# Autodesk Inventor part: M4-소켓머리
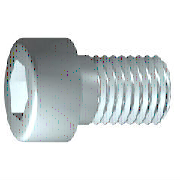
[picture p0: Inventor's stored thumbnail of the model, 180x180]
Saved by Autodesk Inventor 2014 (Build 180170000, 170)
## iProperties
IsCustomPart: 0
Created: 2009-02
Part Number: M4-소켓머리
Material: 강, 연강
Description: 6각머리 태핑 나사
Document SubType Name: Modeling
Standard: KS B 1003
Designer: 한국산업디자인학원 [http://gmhk.co.kr]
Standards Organization: KS
Language: ko-KR
Size Designation: M 4 x 12
Categories: <MemberInstance><Categories><Category DisplayName="조임쇠" InternalName="e4da775c-781d-43d5-af7c-5136215cf5a6" Mnemonic="FSTN"><Category DisplayName="볼트" InternalN
Density: 7.86 g/cm^3
Mass: 2.23465 g
Surface Area: 3.30853 cm^2
Volume: 0.284306 cm^3
Appearance: _시험-금속-강(연마)
Author: pww
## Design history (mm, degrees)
sketch "스케치1"
  geometry: L1 (-1, 0)-(12, 0); L2 (12, 0)-(12, 2); L3 (12, 2)-(1.75, 2); L4 (1.75, 2)-(1.32, 2); L5 (1.32, 2)-(0, 2); L6 (0, 2)-(0, 3.5); L7 (0, 3.5)-(-4, 3.5); L8 (-4, 3.5)-(-4, 1.732); L9 (-4, 1.732)-(-2, 1.732); L10 (-2, 1.732)-(-1, 0); L11 (-7.2, 0)-(15.2, 0) reference; L12 (0, -0.7)-(0, 4.2) reference; L13 (1.75, 2)-(0, 2)
  constraints: 22 end point, 6 parallel, 2 collinear, 2 perpendicular, 1 horizontal, 1 point on line
  dimensions: "d1" = 10.25 distance from line of L3.end L2 (= GEL); "d2" = 0.42952 distance of L4.end L3.end (computed from GAL); "d3" = 4 distance between parallel lines of L8 L6 (= KOH); "d4" = 2 distance of L8.end L9.end (= INTI); "d5" = 60 deg angle of L10 L1; "d6" = 4 diameter of L3 L1 (= GD); "d7" = 4 diameter of L5 L1 (= BDM); "d8" = 3.4641 diameter of L9 L1 (= 1.1547 x SW); "d9" = 7 diameter of L7 L1 (= KOD); "d26" = 12 distance between parallel lines of L12 L2 (= NLG)
revolve "본체" sketch "스케치1" stored, may be unused: angle "d10" = 90 deg
sketch "스케치2"
  geometry: L1 (0, -4.9)-(0, 4.9) reference; L2 (-4.9, 0)-(4.9, 0) reference; L3 (1.732, 0)-(0.866, -1.5); L4 (0.866, -1.5)-(-0.866, -1.5); L5 (-0.866, -1.5)-(-1.732, 0); L6 (-1.732, 0)-(-0.866, 1.5); L7 (-0.866, 1.5)-(0.866, 1.5); L8 (0.866, 1.5)-(1.732, 0); 2 further points
  constraints: 12 end point, 1 coincident, 1 horizontal alignment, 1 point on line, 12 other
extrude "슬롯" join sketch "스케치2" stored distance "d11" = 10; taper "d12" = 0 deg
workplane "Work Plane1"
fillet "Fillet2" dims "d30" = 0.1 (= R)
body "Solid1"
fillet "모깎기1" dims "d17" = 0.4 (= RR)
feature "스레드" dims "d13" = 10.25 (= GEL), "d14" = 0
chamfer "모따기1" distance "d15" = 0.42941 (= -0.5 x SPD + 0.5 x GD); stored, may be unused: second distance "d16" = 0.42941 (= GUL), angle "d27" = 45 deg
other parameters: "GD" = 4 (= NND) [user parameter; used in 2 equation terms], "NLG" = 12 [user parameter; used in 1 equation term], "GEL" = 10.25 [user parameter; used in 2 equation terms], "KOD" = 7 [user parameter; used in 1 equation term], "KOH" = 4 [user parameter; used in 1 equation term], "INTI" = 2 [user parameter; used in 1 equation term], "GAL" = 0.42941 (= 0.61345 x PTC) [user parameter; used in 1 equation term], "GUL" = 0.42941 (= 0.61345 x PTC) [user parameter; used in 1 equation term], "BDM" = 4 (= NND) [user parameter; used in 1 equation term], "SW" = 3 [user parameter; used in 2 equation terms], "RR" = 0.4 [user parameter; used in 1 equation term], "SPD" = 3.14117 (= NND - 1.2269 x PTC) [user parameter; used in 1 equation term], "d19" = 0, "d28" = 0, "d29" = 0, "R" = 0.1 [user parameter; used in 1 equation term], "PHH" = 0.2 [user parameter], "GD1" = 3.14117 (= THREADDIA - 1.2269 x PTC) [user parameter], "THREADDIA" = 4 [user parameter; used in 1 equation term], "FAWI" = 45 deg [user parameter], "TPU" = 14.28571 (computed from PTC) [user parameter], "PTC" = 0.7 [user parameter; used in 5 equation terms], "NND" = 4 [user parameter; used in 3 equation terms], "TOA" = 30 deg [user parameter], "E0" = 3.465 (= 1.155 x SW) [user parameter]
